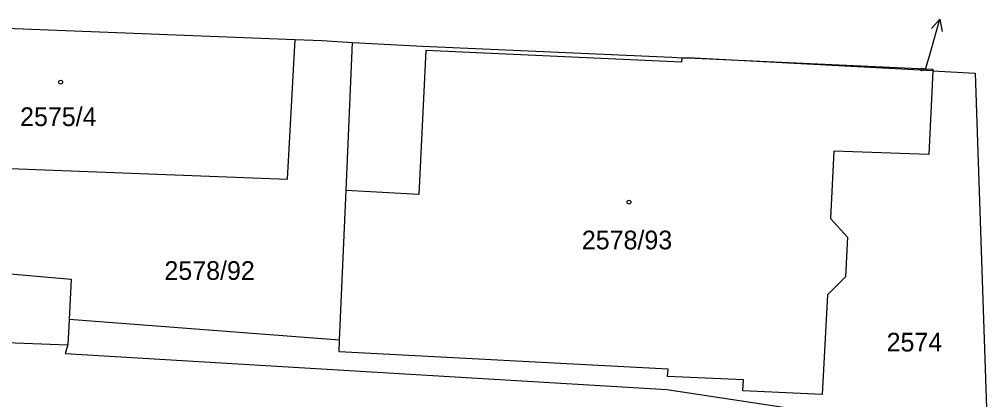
# Model space of a CAD drawing. Extents: x -527335 to -526256, y -1079142 to -1077836.
# Drawn here: x -526700.3 to -526612.3, y -1078290.8 to -1078256.2 of the extents above; entities that cross this region are included whole.
import ezdxf

# ---------------------------------------------------------------- set-up
doc = ezdxf.new("R2010")
doc.units = 0
for name, color, linetype in [('Hranice parcel', 7, 'Continuous'), ('Parcelní čísla', 7, 'Continuous'), ('Pop  PČ popisy', 7, 'Continuous'), ('Vnitřní kresba', 7, 'Continuous'), ('Značky budov', 7, 'Continuous')]:
    doc.layers.add(name, color=color, linetype=linetype)

msp = doc.modelspace()

# ---------------------------------------------------------------- linework, layer by layer
at = {"layer": 'Hranice parcel'}
for p, q in [((-526717.88, -1078256.37), (-526675.26, -1078258.03)), ((-526617.25, -1078260.89), (-526639.54, -1078259.71)), ((-526617.25, -1078260.89), (-526613.4, -1078261.09)), ((-526613.4, -1078261.09), (-526612.35, -1078291.6)), ((-526695.81, -1078283.53), (-526695.92, -1078285.82)), ((-526671.21, -1078285.41), (-526695.81, -1078283.53)), ((-526719.79, -1078284.89), (-526695.92, -1078285.82))]:
    msp.add_line(p, q, dxfattribs=at)
for points in [[(-526718.54, -1078268.81), (-526718.55, -1078269.1), (-526675.94, -1078270.75), (-526675.26, -1078258.03)], [(-526675.26, -1078258.03), (-526672.79, -1078258.13), (-526670.02, -1078258.29)], [(-526671.21, -1078285.41), (-526670.67, -1078273.12), (-526670.61, -1078271.78), (-526670.02, -1078258.29)], [(-526670.02, -1078258.29), (-526663.67, -1078258.65), (-526640.99, -1078259.65), (-526640.08, -1078259.69), (-526639.54, -1078259.71)], [(-526639.54, -1078259.71), (-526617.24, -1078260.72), (-526617.25, -1078260.89)], [(-526617.25, -1078260.89), (-526617.62, -1078268.51), (-526626.24, -1078268.19), (-526626.56, -1078274.33), (-526625.01, -1078276.02), (-526625.18, -1078279.62), (-526626.84, -1078281.28), (-526627.3, -1078290.35), (-526634.53, -1078290.02), (-526634.47, -1078289), (-526641.38, -1078288.71), (-526641.33, -1078288.04), (-526671.26, -1078286.45), (-526671.21, -1078285.41)], [(-526719.23, -1078270.66), (-526708.29, -1078271.04), (-526708.33, -1078271.55), (-526708.81, -1078278.7), (-526695.63, -1078279.84), (-526695.81, -1078283.53)], [(-526695.92, -1078285.82), (-526696.17, -1078286.6), (-526641.44, -1078289.9), (-526627.42, -1078292.02), (-526614.86, -1078298.09), (-526612.81, -1078296.77), (-526612.35, -1078291.6)]]:
    msp.add_lwpolyline(points, dxfattribs=at)
at = {"layer": 'Pop  PČ popisy'}
for p, q in [((-526617.43, -1078259.08), (-526616.603, -1078256.195)), ((-526616.603, -1078256.195), (-526617.36, -1078257.02)), ((-526616.603, -1078256.195), (-526616.398, -1078257.296)), ((-526617.9, -1078260.75), (-526617.43, -1078259.08))]:
    msp.add_line(p, q, dxfattribs=at)
at = {"layer": 'Vnitřní kresba'}
for p, q in [((-526663.35, -1078259.03), (-526664, -1078272.15)), ((-526640.1, -1078260.09), (-526663.35, -1078259.03)), ((-526640.08, -1078259.69), (-526640.1, -1078260.09)), ((-526664, -1078272.15), (-526670.61, -1078271.78))]:
    msp.add_line(p, q, dxfattribs=at)
at = {"layer": 'Značky budov'}
for centre, radius in [((-526618.205, -1078260.759), 0.117), ((-526696.577, -1078261.909), 0.175), ((-526644.887, -1078272.839), 0.175)]:
    msp.add_circle(centre, radius, dxfattribs=at)

# ---------------------------------------------------------------- texts
at = {"layer": 'Parcelní čísla'}
for s, p in [('2575/4', (-526700.27, -1078265.91)), ('2578/93', (-526649.17, -1078277.13)), ('2578/92', (-526687.14, -1078279.91)), ('2574', (-526621.449, -1078286.43))]:
    msp.add_text(s, height=1.7, dxfattribs=at).set_placement(p)

doc.saveas('drawing.dxf')
